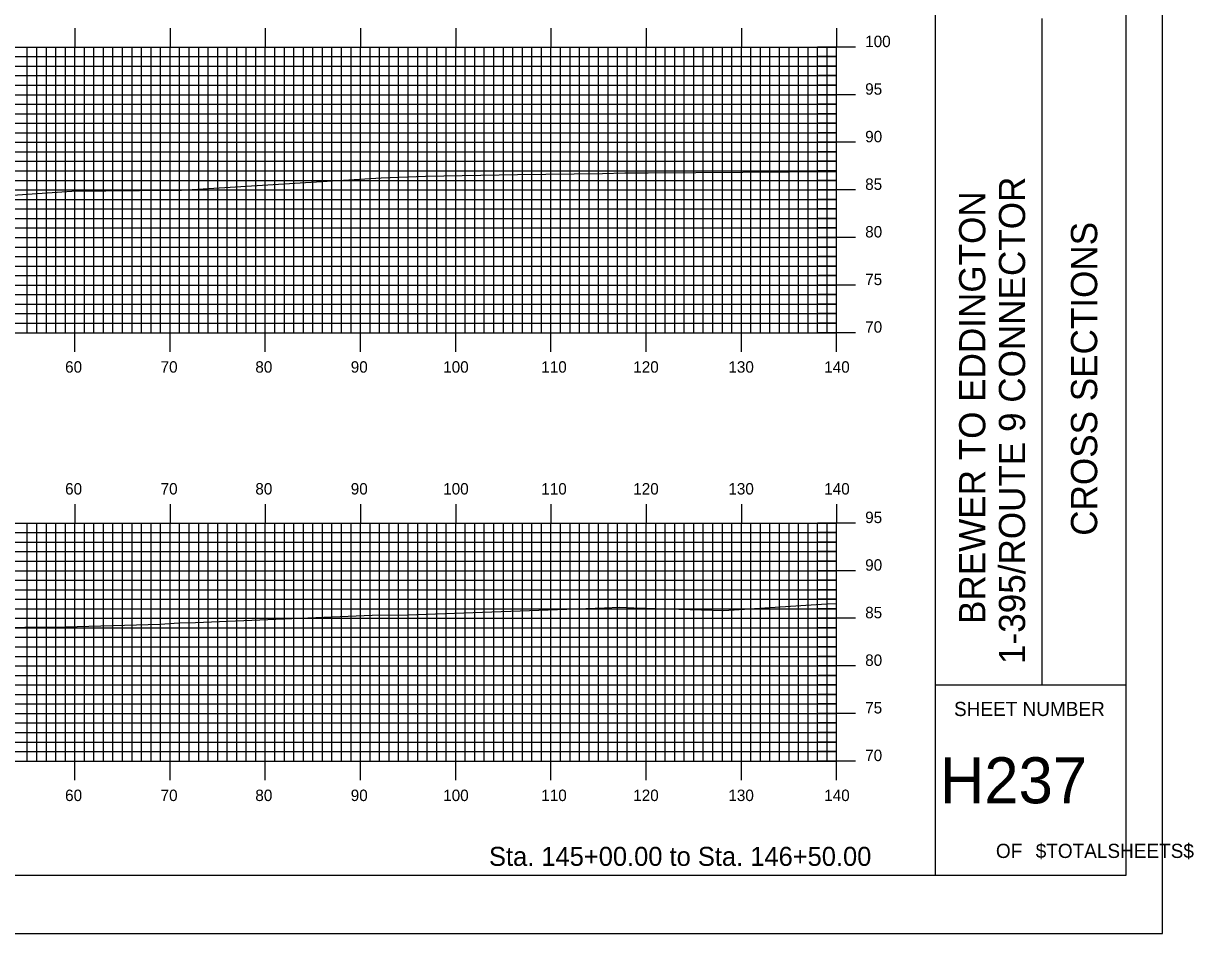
# Model space of a CAD drawing. Extents: x 1777531 to 1777875, y 442591 to 442811.
# Drawn here: x 1777751.9 to 1777874.8, y 442590.5 to 442686.2 of the extents above; entities that cross this region are included whole.
import ezdxf

# ---------------------------------------------------------------- set-up
doc = ezdxf.new("R2010")
doc.units = 0
for name, color, linetype in [('BORDER', 7, 'Continuous'), ('H_V ANNOTATION', 7, 'Continuous'), ('MAJOR', 7, 'Continuous'), ('MINOR', 7, 'Continuous'), ('PLOT BOUNDARY', 7, 'Continuous'), ('S_Roadway_Centerline', 7, 'Continuous')]:
    doc.layers.add(name, color=color, linetype=linetype)

msp = doc.modelspace()

# ---------------------------------------------------------------- linework, layer by layer
at = {"layer": 'BORDER'}
for p, q in [((1777847.68, 442596.67), (1777847.68, 442806.67)), ((1777858.86, 442616.67), (1777858.86, 442686.67)), ((1777847.68, 442616.67), (1777867.68, 442616.67))]:
    msp.add_line(p, q, dxfattribs=at)
msp.add_lwpolyline([(1777547.68, 442596.67), (1777867.68, 442596.67), (1777867.68, 442806.67), (1777547.68, 442806.67)], close=True, dxfattribs=at)
at = {"layer": 'MAJOR'}
for p, q in [((1777757.28, 442685.67), (1777757.28, 442683.67)), ((1777767.28, 442685.67), (1777767.28, 442683.67)), ((1777777.28, 442685.67), (1777777.28, 442683.67)), ((1777787.28, 442685.67), (1777787.28, 442683.67)), ((1777797.28, 442685.67), (1777797.28, 442683.67)), ((1777807.28, 442685.67), (1777807.28, 442683.67)), ((1777817.28, 442685.67), (1777817.28, 442683.67)), ((1777827.28, 442685.67), (1777827.28, 442683.67)), ((1777837.28, 442685.67), (1777837.28, 442683.67)), ((1777557.28, 442683.67), (1777837.28, 442683.67)), ((1777557.28, 442683.67), (1777837.28, 442683.67)), ((1777757.28, 442653.67), (1777757.28, 442683.67)), ((1777767.28, 442653.67), (1777767.28, 442683.67)), ((1777777.28, 442653.67), (1777777.28, 442683.67)), ((1777787.28, 442653.67), (1777787.28, 442683.67)), ((1777797.28, 442653.67), (1777797.28, 442683.67)), ((1777807.28, 442653.67), (1777807.28, 442683.67)), ((1777817.28, 442653.67), (1777817.28, 442683.67)), ((1777827.28, 442653.67), (1777827.28, 442683.67)), ((1777839.28, 442683.67), (1777835.27, 442683.67)), ((1777837.28, 442653.67), (1777837.28, 442683.67)), ((1777837.28, 442653.67), (1777837.28, 442683.67)), ((1777557.28, 442678.67), (1777837.28, 442678.67)), ((1777839.28, 442678.67), (1777835.27, 442678.67)), ((1777557.28, 442673.67), (1777837.28, 442673.67)), ((1777839.28, 442673.67), (1777835.27, 442673.67)), ((1777557.28, 442668.67), (1777837.28, 442668.67)), ((1777839.28, 442668.67), (1777835.27, 442668.67)), ((1777557.28, 442663.67), (1777837.28, 442663.67)), ((1777839.28, 442663.67), (1777835.27, 442663.67)), ((1777557.28, 442658.67), (1777837.28, 442658.67)), ((1777839.28, 442658.67), (1777835.27, 442658.67)), ((1777557.28, 442653.67), (1777837.28, 442653.67)), ((1777557.28, 442653.67), (1777837.28, 442653.67)), ((1777757.28, 442651.66), (1777757.28, 442653.67)), ((1777767.28, 442651.66), (1777767.28, 442653.67)), ((1777777.28, 442651.66), (1777777.28, 442653.67)), ((1777787.28, 442651.66), (1777787.28, 442653.67)), ((1777797.28, 442651.66), (1777797.28, 442653.67)), ((1777807.28, 442651.66), (1777807.28, 442653.67)), ((1777817.28, 442651.66), (1777817.28, 442653.67)), ((1777827.28, 442651.66), (1777827.28, 442653.67)), ((1777839.28, 442653.67), (1777835.27, 442653.67)), ((1777837.28, 442651.66), (1777837.28, 442653.67)), ((1777757.28, 442635.67), (1777757.28, 442633.67)), ((1777767.28, 442635.67), (1777767.28, 442633.67)), ((1777777.28, 442635.67), (1777777.28, 442633.67)), ((1777787.28, 442635.67), (1777787.28, 442633.67)), ((1777797.28, 442635.67), (1777797.28, 442633.67)), ((1777807.28, 442635.67), (1777807.28, 442633.67)), ((1777817.28, 442635.67), (1777817.28, 442633.67)), ((1777827.28, 442635.67), (1777827.28, 442633.67)), ((1777837.28, 442635.67), (1777837.28, 442633.67)), ((1777557.28, 442633.67), (1777837.28, 442633.67)), ((1777557.28, 442633.67), (1777837.28, 442633.67)), ((1777757.28, 442608.67), (1777757.28, 442633.67)), ((1777767.28, 442608.67), (1777767.28, 442633.67)), ((1777777.28, 442608.67), (1777777.28, 442633.67)), ((1777787.28, 442608.67), (1777787.28, 442633.67)), ((1777797.28, 442608.67), (1777797.28, 442633.67)), ((1777807.28, 442608.67), (1777807.28, 442633.67)), ((1777817.28, 442608.67), (1777817.28, 442633.67)), ((1777827.28, 442608.67), (1777827.28, 442633.67)), ((1777839.28, 442633.67), (1777835.27, 442633.67)), ((1777837.28, 442608.67), (1777837.28, 442633.67)), ((1777837.28, 442608.67), (1777837.28, 442633.67)), ((1777557.28, 442628.67), (1777837.28, 442628.67)), ((1777839.28, 442628.67), (1777835.27, 442628.67)), ((1777557.28, 442623.67), (1777837.28, 442623.67)), ((1777839.28, 442623.67), (1777835.27, 442623.67)), ((1777557.28, 442618.67), (1777837.28, 442618.67)), ((1777839.28, 442618.67), (1777835.27, 442618.67)), ((1777557.28, 442613.67), (1777837.28, 442613.67)), ((1777839.28, 442613.67), (1777835.27, 442613.67)), ((1777557.28, 442608.67), (1777837.28, 442608.67)), ((1777557.28, 442608.67), (1777837.28, 442608.67)), ((1777757.28, 442606.66), (1777757.28, 442608.67)), ((1777767.28, 442606.66), (1777767.28, 442608.67)), ((1777777.28, 442606.66), (1777777.28, 442608.67)), ((1777787.28, 442606.66), (1777787.28, 442608.67)), ((1777797.28, 442606.66), (1777797.28, 442608.67)), ((1777807.28, 442606.66), (1777807.28, 442608.67)), ((1777817.28, 442606.66), (1777817.28, 442608.67)), ((1777827.28, 442606.66), (1777827.28, 442608.67)), ((1777839.28, 442608.67), (1777835.27, 442608.67)), ((1777837.28, 442606.66), (1777837.28, 442608.67))]:
    msp.add_line(p, q, dxfattribs=at)
at = {"layer": 'MINOR'}
for p, q in [((1777752.28, 442653.67), (1777752.28, 442683.67)), ((1777753.28, 442653.67), (1777753.28, 442683.67)), ((1777754.28, 442653.67), (1777754.28, 442683.67)), ((1777755.28, 442653.67), (1777755.28, 442683.67)), ((1777756.28, 442653.67), (1777756.28, 442683.67)), ((1777758.28, 442653.67), (1777758.28, 442683.67)), ((1777759.28, 442653.67), (1777759.28, 442683.67)), ((1777760.28, 442653.67), (1777760.28, 442683.67)), ((1777761.28, 442653.67), (1777761.28, 442683.67)), ((1777762.28, 442653.67), (1777762.28, 442683.67)), ((1777763.28, 442653.67), (1777763.28, 442683.67)), ((1777764.28, 442653.67), (1777764.28, 442683.67)), ((1777765.28, 442653.67), (1777765.28, 442683.67)), ((1777766.28, 442653.67), (1777766.28, 442683.67)), ((1777768.28, 442653.67), (1777768.28, 442683.67)), ((1777769.28, 442653.67), (1777769.28, 442683.67)), ((1777770.28, 442653.67), (1777770.28, 442683.67)), ((1777771.28, 442653.67), (1777771.28, 442683.67)), ((1777772.28, 442653.67), (1777772.28, 442683.67)), ((1777773.28, 442653.67), (1777773.28, 442683.67)), ((1777774.28, 442653.67), (1777774.28, 442683.67)), ((1777775.28, 442653.67), (1777775.28, 442683.67)), ((1777776.28, 442653.67), (1777776.28, 442683.67)), ((1777778.28, 442653.67), (1777778.28, 442683.67)), ((1777779.28, 442653.67), (1777779.28, 442683.67)), ((1777780.28, 442653.67), (1777780.28, 442683.67)), ((1777781.28, 442653.67), (1777781.28, 442683.67)), ((1777782.28, 442653.67), (1777782.28, 442683.67)), ((1777783.28, 442653.67), (1777783.28, 442683.67)), ((1777784.28, 442653.67), (1777784.28, 442683.67)), ((1777785.28, 442653.67), (1777785.28, 442683.67)), ((1777786.28, 442653.67), (1777786.28, 442683.67)), ((1777788.28, 442653.67), (1777788.28, 442683.67)), ((1777789.28, 442653.67), (1777789.28, 442683.67)), ((1777790.28, 442653.67), (1777790.28, 442683.67)), ((1777791.28, 442653.67), (1777791.28, 442683.67)), ((1777792.28, 442653.67), (1777792.28, 442683.67)), ((1777793.28, 442653.67), (1777793.28, 442683.67)), ((1777794.28, 442653.67), (1777794.28, 442683.67)), ((1777795.28, 442653.67), (1777795.28, 442683.67)), ((1777796.28, 442653.67), (1777796.28, 442683.67)), ((1777798.28, 442653.67), (1777798.28, 442683.67)), ((1777799.28, 442653.67), (1777799.28, 442683.67)), ((1777800.28, 442653.67), (1777800.28, 442683.67)), ((1777801.28, 442653.67), (1777801.28, 442683.67)), ((1777802.28, 442653.67), (1777802.28, 442683.67)), ((1777803.28, 442653.67), (1777803.28, 442683.67)), ((1777804.28, 442653.67), (1777804.28, 442683.67)), ((1777805.28, 442653.67), (1777805.28, 442683.67)), ((1777806.28, 442653.67), (1777806.28, 442683.67)), ((1777808.28, 442653.67), (1777808.28, 442683.67)), ((1777809.28, 442653.67), (1777809.28, 442683.67)), ((1777810.28, 442653.67), (1777810.28, 442683.67)), ((1777811.28, 442653.67), (1777811.28, 442683.67)), ((1777812.28, 442653.67), (1777812.28, 442683.67)), ((1777813.28, 442653.67), (1777813.28, 442683.67)), ((1777814.28, 442653.67), (1777814.28, 442683.67)), ((1777815.28, 442653.67), (1777815.28, 442683.67)), ((1777816.28, 442653.67), (1777816.28, 442683.67)), ((1777818.28, 442653.67), (1777818.28, 442683.67)), ((1777819.28, 442653.67), (1777819.28, 442683.67)), ((1777820.28, 442653.67), (1777820.28, 442683.67)), ((1777821.28, 442653.67), (1777821.28, 442683.67)), ((1777822.28, 442653.67), (1777822.28, 442683.67)), ((1777823.28, 442653.67), (1777823.28, 442683.67)), ((1777824.28, 442653.67), (1777824.28, 442683.67)), ((1777825.28, 442653.67), (1777825.28, 442683.67)), ((1777826.28, 442653.67), (1777826.28, 442683.67)), ((1777828.28, 442653.67), (1777828.28, 442683.67)), ((1777829.28, 442653.67), (1777829.28, 442683.67)), ((1777830.28, 442653.67), (1777830.28, 442683.67)), ((1777831.28, 442653.67), (1777831.28, 442683.67)), ((1777832.28, 442653.67), (1777832.28, 442683.67)), ((1777833.28, 442653.67), (1777833.28, 442683.67)), ((1777834.28, 442653.67), (1777834.28, 442683.67)), ((1777835.28, 442653.67), (1777835.28, 442683.67)), ((1777836.28, 442653.67), (1777836.28, 442683.67)), ((1777557.28, 442682.67), (1777837.28, 442682.67)), ((1777837.28, 442682.67), (1777835.27, 442682.67)), ((1777557.28, 442681.67), (1777837.28, 442681.67)), ((1777837.28, 442681.67), (1777835.27, 442681.67)), ((1777557.28, 442680.67), (1777837.28, 442680.67)), ((1777557.28, 442679.67), (1777837.28, 442679.67)), ((1777837.28, 442680.67), (1777835.27, 442680.67)), ((1777837.28, 442679.67), (1777835.27, 442679.67)), ((1777557.28, 442677.67), (1777837.28, 442677.67)), ((1777837.28, 442677.67), (1777835.27, 442677.67)), ((1777557.28, 442676.67), (1777837.28, 442676.67)), ((1777837.28, 442676.67), (1777835.27, 442676.67)), ((1777557.28, 442675.67), (1777837.28, 442675.67)), ((1777557.28, 442674.67), (1777837.28, 442674.67)), ((1777837.28, 442675.67), (1777835.27, 442675.67)), ((1777837.28, 442674.67), (1777835.27, 442674.67)), ((1777557.28, 442672.67), (1777837.28, 442672.67)), ((1777837.28, 442672.67), (1777835.27, 442672.67)), ((1777557.28, 442671.67), (1777837.28, 442671.67)), ((1777837.28, 442671.67), (1777835.27, 442671.67)), ((1777557.28, 442670.67), (1777837.28, 442670.67)), ((1777557.28, 442669.67), (1777837.28, 442669.67)), ((1777837.28, 442670.67), (1777835.27, 442670.67)), ((1777837.28, 442669.67), (1777835.27, 442669.67)), ((1777557.28, 442667.67), (1777837.28, 442667.67)), ((1777837.28, 442667.67), (1777835.27, 442667.67)), ((1777557.28, 442666.67), (1777837.28, 442666.67)), ((1777837.28, 442666.67), (1777835.27, 442666.67)), ((1777557.28, 442665.67), (1777837.28, 442665.67)), ((1777837.28, 442665.67), (1777835.27, 442665.67)), ((1777557.28, 442664.67), (1777837.28, 442664.67)), ((1777837.28, 442664.67), (1777835.27, 442664.67)), ((1777557.28, 442662.67), (1777837.28, 442662.67)), ((1777837.28, 442662.67), (1777835.27, 442662.67)), ((1777557.28, 442661.67), (1777837.28, 442661.67)), ((1777837.28, 442661.67), (1777835.27, 442661.67)), ((1777557.28, 442660.67), (1777837.28, 442660.67)), ((1777837.28, 442660.67), (1777835.27, 442660.67)), ((1777557.28, 442659.67), (1777837.28, 442659.67)), ((1777837.28, 442659.67), (1777835.27, 442659.67)), ((1777557.28, 442657.67), (1777837.28, 442657.67)), ((1777837.28, 442657.67), (1777835.27, 442657.67)), ((1777557.28, 442656.67), (1777837.28, 442656.67)), ((1777837.28, 442656.67), (1777835.27, 442656.67)), ((1777557.28, 442655.67), (1777837.28, 442655.67)), ((1777837.28, 442655.67), (1777835.27, 442655.67)), ((1777557.28, 442654.67), (1777837.28, 442654.67)), ((1777837.28, 442654.67), (1777835.27, 442654.67)), ((1777752.28, 442608.67), (1777752.28, 442633.67)), ((1777753.28, 442608.67), (1777753.28, 442633.67)), ((1777754.28, 442608.67), (1777754.28, 442633.67)), ((1777755.28, 442608.67), (1777755.28, 442633.67)), ((1777756.28, 442608.67), (1777756.28, 442633.67)), ((1777758.28, 442608.67), (1777758.28, 442633.67)), ((1777759.28, 442608.67), (1777759.28, 442633.67)), ((1777760.28, 442608.67), (1777760.28, 442633.67)), ((1777761.28, 442608.67), (1777761.28, 442633.67)), ((1777762.28, 442608.67), (1777762.28, 442633.67)), ((1777763.28, 442608.67), (1777763.28, 442633.67)), ((1777764.28, 442608.67), (1777764.28, 442633.67)), ((1777765.28, 442608.67), (1777765.28, 442633.67)), ((1777766.28, 442608.67), (1777766.28, 442633.67)), ((1777768.28, 442608.67), (1777768.28, 442633.67)), ((1777769.28, 442608.67), (1777769.28, 442633.67)), ((1777770.28, 442608.67), (1777770.28, 442633.67)), ((1777771.28, 442608.67), (1777771.28, 442633.67)), ((1777772.28, 442608.67), (1777772.28, 442633.67)), ((1777773.28, 442608.67), (1777773.28, 442633.67)), ((1777774.28, 442608.67), (1777774.28, 442633.67)), ((1777775.28, 442608.67), (1777775.28, 442633.67)), ((1777776.28, 442608.67), (1777776.28, 442633.67)), ((1777778.28, 442608.67), (1777778.28, 442633.67)), ((1777779.28, 442608.67), (1777779.28, 442633.67)), ((1777780.28, 442608.67), (1777780.28, 442633.67)), ((1777781.28, 442608.67), (1777781.28, 442633.67)), ((1777782.28, 442608.67), (1777782.28, 442633.67)), ((1777783.28, 442608.67), (1777783.28, 442633.67)), ((1777784.28, 442608.67), (1777784.28, 442633.67)), ((1777785.28, 442608.67), (1777785.28, 442633.67)), ((1777786.28, 442608.67), (1777786.28, 442633.67)), ((1777788.28, 442608.67), (1777788.28, 442633.67)), ((1777789.28, 442608.67), (1777789.28, 442633.67)), ((1777790.28, 442608.67), (1777790.28, 442633.67)), ((1777791.28, 442608.67), (1777791.28, 442633.67)), ((1777792.28, 442608.67), (1777792.28, 442633.67)), ((1777793.28, 442608.67), (1777793.28, 442633.67)), ((1777794.28, 442608.67), (1777794.28, 442633.67)), ((1777795.28, 442608.67), (1777795.28, 442633.67)), ((1777796.28, 442608.67), (1777796.28, 442633.67)), ((1777798.28, 442608.67), (1777798.28, 442633.67)), ((1777799.28, 442608.67), (1777799.28, 442633.67)), ((1777800.28, 442608.67), (1777800.28, 442633.67)), ((1777801.28, 442608.67), (1777801.28, 442633.67)), ((1777802.28, 442608.67), (1777802.28, 442633.67)), ((1777803.28, 442608.67), (1777803.28, 442633.67)), ((1777804.28, 442608.67), (1777804.28, 442633.67)), ((1777805.28, 442608.67), (1777805.28, 442633.67)), ((1777806.28, 442608.67), (1777806.28, 442633.67)), ((1777808.28, 442608.67), (1777808.28, 442633.67)), ((1777809.28, 442608.67), (1777809.28, 442633.67)), ((1777810.28, 442608.67), (1777810.28, 442633.67)), ((1777811.28, 442608.67), (1777811.28, 442633.67)), ((1777812.28, 442608.67), (1777812.28, 442633.67)), ((1777813.28, 442608.67), (1777813.28, 442633.67)), ((1777814.28, 442608.67), (1777814.28, 442633.67)), ((1777815.28, 442608.67), (1777815.28, 442633.67)), ((1777816.28, 442608.67), (1777816.28, 442633.67)), ((1777818.28, 442608.67), (1777818.28, 442633.67)), ((1777819.28, 442608.67), (1777819.28, 442633.67)), ((1777820.28, 442608.67), (1777820.28, 442633.67)), ((1777821.28, 442608.67), (1777821.28, 442633.67)), ((1777822.28, 442608.67), (1777822.28, 442633.67)), ((1777823.28, 442608.67), (1777823.28, 442633.67)), ((1777824.28, 442608.67), (1777824.28, 442633.67)), ((1777825.28, 442608.67), (1777825.28, 442633.67)), ((1777826.28, 442608.67), (1777826.28, 442633.67)), ((1777828.28, 442608.67), (1777828.28, 442633.67)), ((1777829.28, 442608.67), (1777829.28, 442633.67)), ((1777830.28, 442608.67), (1777830.28, 442633.67)), ((1777831.28, 442608.67), (1777831.28, 442633.67)), ((1777832.28, 442608.67), (1777832.28, 442633.67)), ((1777833.28, 442608.67), (1777833.28, 442633.67)), ((1777834.28, 442608.67), (1777834.28, 442633.67)), ((1777835.28, 442608.67), (1777835.28, 442633.67)), ((1777836.28, 442608.67), (1777836.28, 442633.67)), ((1777557.28, 442632.67), (1777837.28, 442632.67)), ((1777557.28, 442631.67), (1777837.28, 442631.67)), ((1777837.28, 442632.67), (1777835.27, 442632.67)), ((1777837.28, 442631.67), (1777835.27, 442631.67)), ((1777557.28, 442630.67), (1777837.28, 442630.67)), ((1777837.28, 442630.67), (1777835.27, 442630.67)), ((1777557.28, 442629.67), (1777837.28, 442629.67)), ((1777837.28, 442629.67), (1777835.27, 442629.67)), ((1777557.28, 442627.67), (1777837.28, 442627.67)), ((1777557.28, 442626.67), (1777837.28, 442626.67)), ((1777837.28, 442627.67), (1777835.27, 442627.67)), ((1777837.28, 442626.67), (1777835.27, 442626.67)), ((1777557.28, 442625.67), (1777837.28, 442625.67)), ((1777837.28, 442625.67), (1777835.27, 442625.67)), ((1777557.28, 442624.67), (1777837.28, 442624.67)), ((1777837.28, 442624.67), (1777835.27, 442624.67)), ((1777557.28, 442622.67), (1777837.28, 442622.67)), ((1777837.28, 442622.67), (1777835.27, 442622.67)), ((1777557.28, 442621.67), (1777837.28, 442621.67)), ((1777557.28, 442620.67), (1777837.28, 442620.67)), ((1777837.28, 442621.67), (1777835.27, 442621.67)), ((1777837.28, 442620.67), (1777835.27, 442620.67)), ((1777557.28, 442619.67), (1777837.28, 442619.67)), ((1777837.28, 442619.67), (1777835.27, 442619.67)), ((1777557.28, 442617.67), (1777837.28, 442617.67)), ((1777837.28, 442617.67), (1777835.27, 442617.67)), ((1777557.28, 442616.67), (1777837.28, 442616.67)), ((1777557.28, 442615.67), (1777837.28, 442615.67)), ((1777837.28, 442616.67), (1777835.27, 442616.67)), ((1777837.28, 442615.67), (1777835.27, 442615.67)), ((1777557.28, 442614.67), (1777837.28, 442614.67)), ((1777837.28, 442614.67), (1777835.27, 442614.67)), ((1777557.28, 442612.67), (1777837.28, 442612.67)), ((1777837.28, 442612.67), (1777835.27, 442612.67)), ((1777557.28, 442611.67), (1777837.28, 442611.67)), ((1777557.28, 442610.67), (1777837.28, 442610.67)), ((1777837.28, 442611.67), (1777835.27, 442611.67)), ((1777837.28, 442610.67), (1777835.27, 442610.67)), ((1777557.28, 442609.67), (1777837.28, 442609.67)), ((1777837.28, 442609.67), (1777835.27, 442609.67))]:
    msp.add_line(p, q, dxfattribs=at)
at = {"layer": 'PLOT BOUNDARY'}
msp.add_lwpolyline([(1777531.49, 442590.55), (1777871.49, 442590.55), (1777871.49, 442810.55), (1777531.49, 442810.55)], close=True, dxfattribs=at)
at = {"layer": 'S_Roadway_Centerline'}
for points in [[(1777745.5, 442667.78), (1777756.94, 442668.54), (1777767.62, 442668.64), (1777768.47, 442668.65), (1777789.45, 442669.95), (1777794.09, 442670.12), (1777803.77, 442670.27), (1777812.69, 442670.4), (1777815.02, 442670.45), (1777817.48, 442670.45), (1777822.49, 442670.49), (1777837.28, 442670.59)], [(1777747.72, 442622.71), (1777756.24, 442622.76), (1777766.23, 442623.04), (1777768.19, 442623.18), (1777769.94, 442623.21), (1777788.51, 442623.98), (1777792.2, 442624.04), (1777812.9, 442624.75), (1777814.47, 442624.82), (1777816, 442624.77), (1777825.44, 442624.49), (1777836.21, 442625.17), (1777837.28, 442625.21)]]:
    msp.add_lwpolyline(points, dxfattribs=at)

# ---------------------------------------------------------------- texts
at = {"layer": 'BORDER'}
for s, p in [('1-395/ROUTE 9 CONNECTOR', (1777857.08, 442618.87)), ('BREWER TO EDDINGTON', (1777852.9, 442623.07)), ('CROSS SECTIONS', (1777864.65, 442632.34))]:
    msp.add_text(s, height=2.7557, rotation=90, dxfattribs=at).set_placement(p)
for s, height, p in [('SHEET NUMBER', 1.4905, (1777849.61, 442613.4)), ('H237', 4.839, (1777848.12, 442604.23)), ('OF', 1.491, (1777854.01, 442598.49)), ('$TOTALSHEETS$', 1.4905, (1777858.19, 442598.49))]:
    msp.add_text(s, height=height, dxfattribs=at).set_placement(p)
at = {"layer": 'H_V ANNOTATION'}
for s, height, p in [('100', 1.2, (1777840.28, 442683.67)), ('95', 1.2, (1777840.28, 442678.67)), ('90', 1.2, (1777840.28, 442673.67)), ('85', 1.2, (1777840.28, 442668.67)), ('80', 1.2, (1777840.28, 442663.67)), ('75', 1.2, (1777840.28, 442658.67)), ('70', 1.2, (1777840.28, 442653.67)), ('60', 1.2, (1777756.25, 442649.47)), ('70', 1.2, (1777766.28, 442649.47)), ('80', 1.2, (1777776.23, 442649.47)), ('90', 1.2, (1777786.25, 442649.47)), ('100', 1.2, (1777795.96, 442649.47)), ('110', 1.2, (1777806.26, 442649.47)), ('120', 1.2, (1777815.92, 442649.47)), ('130', 1.2, (1777825.91, 442649.47)), ('140', 1.2, (1777835.98, 442649.47)), ('60', 1.2, (1777756.25, 442636.67)), ('70', 1.2, (1777766.28, 442636.67)), ('80', 1.2, (1777776.23, 442636.67)), ('90', 1.2, (1777786.25, 442636.67)), ('100', 1.2, (1777795.96, 442636.67)), ('110', 1.2, (1777806.26, 442636.67)), ('120', 1.2, (1777815.92, 442636.67)), ('130', 1.2, (1777825.91, 442636.67)), ('140', 1.2, (1777835.98, 442636.67)), ('95', 1.2, (1777840.28, 442633.67)), ('90', 1.2, (1777840.28, 442628.67)), ('85', 1.2, (1777840.28, 442623.67)), ('80', 1.2, (1777840.28, 442618.67)), ('75', 1.2, (1777840.28, 442613.67)), ('70', 1.2, (1777840.28, 442608.67)), ('60', 1.2, (1777756.25, 442604.47)), ('70', 1.2, (1777766.28, 442604.47)), ('80', 1.2, (1777776.23, 442604.47)), ('90', 1.2, (1777786.25, 442604.47)), ('100', 1.2, (1777795.96, 442604.47)), ('110', 1.2, (1777806.26, 442604.47)), ('120', 1.2, (1777815.92, 442604.47)), ('130', 1.2, (1777825.91, 442604.47)), ('140', 1.2, (1777835.98, 442604.47)), ('Sta. 145+00.00 to Sta. 146+50.00', 2.0004, (1777800.77, 442597.66))]:
    msp.add_text(s, height=height, dxfattribs=at).set_placement(p)

doc.saveas('drawing.dxf')
